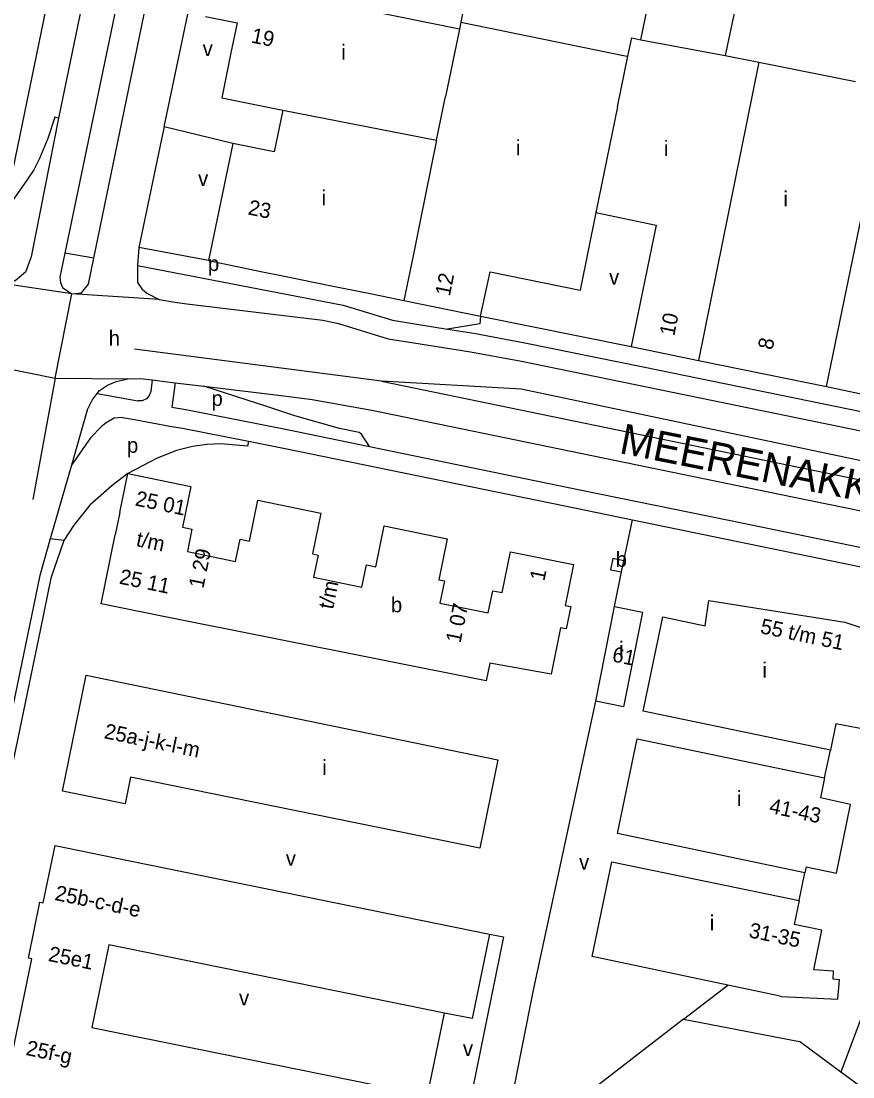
# Model space of a CAD drawing. Extents: x 157699 to 159683, y 381451 to 383293.
# Drawn here: x 158508.3 to 158727.7, y 381916.9 to 382195.6 of the extents above; entities that cross this region are included whole.
import ezdxf

# ---------------------------------------------------------------- set-up
doc = ezdxf.new("R2010")
doc.units = 0
for name, color, linetype in [('BLT_Basislijn', 7, 'Continuous'), ('BLT_Bebouwing', 7, 'Continuous'), ('BLT_Centroide', 7, 'Continuous'), ('BLT_Huisnummer', 7, 'Continuous'), ('BLT_Huisnummer_reeks', 7, 'Continuous'), ('BLT_Onderverdeling_panden', 7, 'Continuous'), ('BLT_Straatnaam_hoofdweg', 7, 'Continuous'), ('BLT_Vlakafsluiter', 7, 'Continuous')]:
    doc.layers.add(name, color=color, linetype=linetype)

msp = doc.modelspace()

# ---------------------------------------------------------------- linework, layer by layer
at = {"layer": 'BLT_Basislijn'}
for p, q in [((158564.13, 382163.27), (158546.04, 382167.67)), ((158527.49, 382132.98), (158519.79, 382134.29)), ((158557.76, 382132.36), (158539.36, 382135.84)), ((158629.49, 382117.65), (158669.22, 382109.67)), ((158517.24, 382101.36), (158511.41, 382069.28)), ((158548.94, 382100.11), (158548.05, 382093.65)), ((158720.79, 382099.1), (158736.46, 382095.81)), ((158667.27, 382053.14), (158669.58, 382063.94)), ((158664.86, 382041.02), (158666.71, 382050.22)), ((158643.57, 381940.24), (158659.86, 382016.04)), ((158720.27, 381995.8), (158721.8, 382003.12)), ((158713.57, 381963.44), (158715.04, 381970.79)), ((158683.01, 381932.1), (158694.72, 381941.12)), ((158615.51, 381911.99), (158619.97, 381933.77)), ((158683.01, 381932.1), (158634.6, 381894.79)), ((158683.01, 381932.1), (158713.62, 381926.26)), ((158724.57, 381918.14), (158713.62, 381926.26)), ((158741.51, 381905.59), (158724.57, 381918.14))]:
    msp.add_line(p, q, dxfattribs=at)
for points in [[(158542.98, 382208.18), (158560.31, 382292.99), (158566.84, 382323.44), (158566.59, 382326.28), (158565.09, 382327.85), (158564.24, 382328.17), (158561.69, 382328.03), (158560.4, 382327.07), (158559.37, 382325.83), (158558.61, 382322.72), (158542.49, 382243.35), (158519.79, 382134.29)], [(158527.49, 382132.98), (158542.98, 382208.18)], [(158524.79, 382202.3), (158518.16, 382169.99)], [(158546.04, 382167.67), (158552.26, 382197.4), (158552.33, 382197.7)], [(158518.16, 382169.99), (158517.16, 382170.25), (158515.34, 382164.61), (158513.1, 382159.29), (158511.61, 382156.3), (158509.83, 382153.6), (158506.57, 382148.93), (158504.42, 382146.04), (158502, 382143.42), (158499.11, 382140.72), (158496.4, 382138.66), (158493.14, 382136.89), (158489.59, 382135.3), (158486.33, 382134.46), (158483.25, 382133.9), (158480.45, 382133.72), (158477.19, 382133.81), (158474.02, 382134.18), (158453.69, 382138.48), (158453.19, 382136.22)], [(158518.16, 382169.99), (158510.96, 382133.33), (158509.41, 382129.31), (158506.7, 382127.02), (158505.37, 382126.57), (158502.18, 382126.47)], [(158546.04, 382167.67), (158545.35, 382164.37), (158539.36, 382135.84)], [(158519.79, 382134.29), (158518.48, 382127.97), (158518.64, 382126.54), (158519.21, 382125.27), (158521.66, 382123.63)], [(158539.36, 382135.84), (158539.01, 382131.03)], [(158521.66, 382123.63), (158524.21, 382123.84), (158526.08, 382126.15), (158527.49, 382132.98)], [(158539.01, 382131.03), (158538.95, 382126.54), (158540.15, 382124.91), (158541.45, 382123.79), (158544.73, 382122.06)], [(158539.01, 382131.03), (158593.27, 382120.63), (158606.26, 382116.63), (158612.64, 382115.59), (158620.77, 382114.29)], [(158544.73, 382122.06), (158548.84, 382121.35), (158552.02, 382120.93), (158587.89, 382116.66), (158592.01, 382115.79), (158605.12, 382111.75), (158611.85, 382110.66), (158626.88, 382108.26), (158640.25, 382105.79), (158773.96, 382078.4), (158781.03, 382076.78)], [(158629.49, 382117.65), (158629.26, 382115.71), (158620.77, 382114.29)], [(158620.77, 382114.29), (158627.72, 382113.18), (158641.21, 382110.69), (158672.43, 382104.3)], [(158603.4, 382100.5), (158538.24, 382108.95)], [(158672.43, 382104.3), (158734.22, 382091.64)], [(158528.37, 382097.25), (158528.97, 382098.04), (158531.05, 382099.44), (158533.35, 382100.44), (158536.53, 382101.17)], [(158536.53, 382101.17), (158539.79, 382101.22), (158542.83, 382100.85)], [(158542.83, 382100.85), (158542.48, 382097.85), (158542.08, 382096.71), (158541.32, 382095.86), (158540.24, 382095.36), (158539.09, 382095.32)], [(158542.83, 382100.85), (158546.21, 382100.44), (158548.94, 382100.11)], [(158548.94, 382100.11), (158556.47, 382099.2)], [(158600.15, 382083.33), (158598.05, 382086.57), (158597.47, 382086.98), (158592.31, 382088.01), (158580.47, 382091.36), (158573.35, 382093.8), (158556.47, 382099.2)], [(158603.4, 382100.5), (158713.37, 382077.85), (158775.69, 382065.11), (158780, 382064.08), (158783.9, 382063.08), (158788, 382061.52), (158792.49, 382059.17)], [(158826.34, 382042.72), (158812.46, 382052.4), (158792.15, 382064.6), (158767.88, 382071.47), (158640.23, 382098.41), (158603.4, 382100.5)], [(158525.75, 382092.88), (158527.03, 382095.5), (158528.37, 382097.25)], [(158528.37, 382097.25), (158539.09, 382095.32)], [(158585.04, 382095.72), (158600.84, 382092.86), (158711.76, 382070.02), (158773.96, 382057.3), (158778.07, 382056.31), (158781.48, 382055.44), (158784.72, 382054.21), (158788.18, 382052.4)], [(158525.75, 382092.88), (158521.58, 382078.35)], [(158548.05, 382093.65), (158551.74, 382093.05), (158578.49, 382087.79), (158600.15, 382083.33)], [(158535, 382090.98), (158532.79, 382090.73), (158530.69, 382089.57), (158529.5, 382088.6), (158526.63, 382085.6), (158521.58, 382078.35)], [(158535, 382090.98), (158538.19, 382090.4), (158547.54, 382088.67), (158550.85, 382088.13), (158568.31, 382084.69)], [(158568.31, 382084.69), (158568.05, 382083.42), (158560.99, 382083.99), (158557.28, 382083.83), (158553.52, 382083.29), (158549.26, 382082.21), (158544.18, 382080.2), (158536.44, 382076.14)], [(158568.31, 382084.69), (158577.5, 382082.89), (158655.14, 382066.9), (158669.58, 382063.94)], [(158600.15, 382083.33), (158656.15, 382071.8), (158694.96, 382063.83), (158732.57, 382056.1), (158748.9, 382052.72), (158774.02, 382047.61), (158776.64, 382046.99), (158779.39, 382046.22), (158782.2, 382045.1), (158784.45, 382043.93), (158786.62, 382042.54), (158789.07, 382040.6), (158791.02, 382038.68), (158792.82, 382036.54)], [(158521.58, 382078.35), (158515.99, 382058.89)], [(158536.44, 382076.14), (158532.32, 382073.02), (158526.43, 382067.83), (158522.18, 382062.49), (158519.56, 382058.47)], [(158669.58, 382063.94), (158693.96, 382058.93), (158731.56, 382051.2), (158734.95, 382050.5)], [(158515.99, 382058.89), (158513.23, 382049.22), (158488.25, 381928.78)], [(158519.56, 382058.47), (158515.99, 382058.89)], [(158519.56, 382058.47), (158516.14, 382048.5), (158513.38, 382035.19)], [(158513.38, 382035.19), (158491.19, 381928.17), (158487.42, 381920.58)], [(158631.83, 381954.62), (158635.53, 381953.87), (158623.19, 381893.31)], [(158640.39, 381924.33), (158643.57, 381940.24)], [(158731.44, 381936.75), (158729.4, 381931.11), (158724.57, 381918.14)], [(158634.6, 381894.79), (158640.39, 381924.33)]]:
    msp.add_lwpolyline(points, dxfattribs=at)
at = {"layer": 'BLT_Bebouwing'}
for p, q in [((158518.94, 382219.05), (158506, 382156.09)), ((158625.29, 382200.03), (158624.32, 382195.29)), ((158556.95, 382196.78), (158565.25, 382195.09)), ((158565.25, 382195.09), (158563.64, 382187.21)), ((158624.32, 382195.29), (158667.62, 382186.44)), ((158667.62, 382186.44), (158668.37, 382186.28)), ((158577.29, 382172.05), (158575.02, 382161.03)), ((158564.13, 382163.27), (158557.76, 382132.36)), ((158575.02, 382161.03), (158564.13, 382163.27)), ((158659.93, 382145.02), (158655.76, 382124.57)), ((158557.76, 382132.36), (158571.99, 382129.43)), ((158571.99, 382129.43), (158577.32, 382128.34)), ((158632.02, 382129.42), (158655.76, 382124.57)), ((158577.32, 382128.34), (158585.38, 382126.7)), ((158585.38, 382126.7), (158590.21, 382125.71)), ((158590.21, 382125.71), (158599.48, 382123.81)), ((158599.48, 382123.81), (158603.38, 382123.02)), ((158603.38, 382123.02), (158609.26, 382121.81)), ((158666.71, 382050.22), (158667.27, 382053.14)), ((158677.59, 382038.35), (158688.71, 382035.93)), ((158525.48, 382022.92), (158634.02, 382000.56)), ((158634.02, 382000.56), (158629.29, 381977.26)), ((158658.96, 381948.67), (158664.13, 381973.71)), ((158510.25, 381948.27), (158513.25, 381963.05)), ((158531.41, 381951.74), (158526.98, 381929.97)), ((158619.97, 381933.77), (158531.41, 381951.74)), ((158505.15, 381918.91), (158511.11, 381948.09)), ((158511.11, 381948.09), (158510.25, 381948.27)), ((158694.72, 381941.12), (158658.96, 381948.67)), ((158708.53, 381938.2), (158694.72, 381941.12)), ((158526.98, 381929.97), (158615.51, 381911.99))]:
    msp.add_line(p, q, dxfattribs=at)
for points in [[(158671.81, 382190.67), (158680.46, 382232.95), (158678.02, 382233.45), (158682.37, 382254.34)], [(158668.37, 382186.28), (158669.37, 382191.17), (158671.81, 382190.67)], [(158563.64, 382187.21), (158561.22, 382175.36), (158577.29, 382172.05)], [(158720.79, 382099.1), (158730.62, 382146.93), (158746.41, 382143.69)], [(158659.93, 382145.02), (158675.79, 382141.74), (158669.22, 382109.67)], [(158629.49, 382117.65), (158632.02, 382129.42)], [(158609.26, 382121.81), (158629.49, 382117.65)], [(158669.22, 382109.67), (158686.96, 382106.03)], [(158686.96, 382106.03), (158720.79, 382099.1)], [(158534.34, 382065.85), (158536.44, 382076.14)], [(158536.44, 382076.14), (158553.1, 382072.73)], [(158553.1, 382072.73), (158550.9, 382061.96), (158553.35, 382061.46), (158552.15, 382055.58), (158564.88, 382052.97)], [(158564.88, 382052.97), (158566.08, 382058.85), (158568.53, 382058.35), (158570.74, 382069.13)], [(158570.74, 382069.13), (158587.39, 382065.72)], [(158534.34, 382065.85), (158533.14, 382059.97)], [(158587.39, 382065.72), (158585.19, 382054.95), (158586.66, 382054.65), (158585.46, 382048.77), (158598.19, 382046.17)], [(158598.19, 382046.17), (158599.4, 382052.04), (158601.84, 382051.54), (158604.05, 382062.32)], [(158604.05, 382062.32), (158620.7, 382058.92)], [(158630.99, 382021.43), (158545.88, 382038.38), (158529.42, 382041.75), (158533.14, 382059.97)], [(158620.7, 382058.92), (158618.5, 382048.14), (158619.97, 382047.84), (158618.77, 382041.96), (158631.51, 382039.36)], [(158631.51, 382039.36), (158632.71, 382045.24), (158635.16, 382044.74), (158637.36, 382055.51)], [(158637.36, 382055.51), (158654.01, 382052.11)], [(158667.27, 382053.14), (158664.37, 382053.7), (158663.8, 382050.78), (158666.71, 382050.22)], [(158654.01, 382052.11), (158651.81, 382041.33), (158653.28, 382041.03)], [(158688.71, 382035.93), (158689.74, 382042.67)], [(158689.74, 382042.67), (158725.62, 382036.91), (158739.81, 382032.19)], [(158653.28, 382041.03), (158652.08, 382035.15), (158650.61, 382035.45), (158648.11, 382023.21), (158631.93, 382026.11), (158630.99, 382021.43)], [(158664.86, 382041.02), (158672.2, 382039.56), (158667.2, 382014.57), (158659.86, 382016.04)], [(158659.86, 382016.04), (158664.86, 382041.02)], [(158721.8, 382003.12), (158672.38, 382013.41), (158677.59, 382038.35)], [(158739.81, 382032.19), (158737.6, 382025.35), (158734.29, 382026.43), (158730.57, 382008.65), (158723.26, 382010.13)], [(158629.29, 381977.26), (158537.16, 381995.98), (158535.73, 381989), (158519.18, 381992.34), (158525.48, 382022.92)], [(158723.26, 382010.13), (158721.8, 382003.12)], [(158715.04, 381970.79), (158665.64, 381981.15), (158670.85, 382006.13)], [(158670.85, 382006.13), (158720.27, 381995.8)], [(158720.27, 381995.8), (158719.19, 381990.57)], [(158715.39, 381972.39), (158723.39, 381970.69), (158727.13, 381988.77), (158719.19, 381990.57)], [(158513.25, 381963.05), (158514.13, 381962.87), (158517.25, 381977.95), (158532.63, 381974.81)], [(158532.63, 381974.81), (158631.83, 381954.62)], [(158664.13, 381973.71), (158713.57, 381963.44)], [(158715.39, 381972.39), (158715.04, 381970.79)], [(158713.57, 381963.44), (158712.25, 381957.14)], [(158724.19, 381942.5), (158722.49, 381942.71), (158722.6, 381944.83), (158717.38, 381945.14), (158719.54, 381955.63), (158712.25, 381957.14)], [(158631.83, 381954.62), (158627.28, 381932.28), (158619.97, 381933.77)], [(158708.53, 381938.2), (158708.84, 381938.14), (158723.75, 381937.43), (158724.19, 381942.5)]]:
    msp.add_lwpolyline(points, dxfattribs=at)
at = {"layer": 'BLT_Onderverdeling_panden'}
for p, q in [((158703.87, 382232.93), (158694.03, 382186.49)), ((158623.95, 382193.48), (158558.96, 382206.64)), ((158623.95, 382193.48), (158620.28, 382175.71)), ((158624.32, 382195.29), (158623.95, 382193.48)), ((158671.81, 382190.67), (158694.03, 382186.49)), ((158665.62, 382172.94), (158668.37, 382186.28)), ((158702.89, 382184.73), (158686.96, 382106.03)), ((158694.03, 382186.49), (158702.89, 382184.73)), ((158702.89, 382184.73), (158728.38, 382179.66)), ((158617.91, 382164.11), (158620.28, 382175.71)), ((158577.29, 382172.05), (158617.91, 382164.11)), ((158665.62, 382172.94), (158659.93, 382145.02)), ((158617.91, 382164.11), (158613.57, 382142.89)), ((158613.57, 382142.89), (158611.67, 382133.58)), ((158611.67, 382133.58), (158609.26, 382121.81))]:
    msp.add_line(p, q, dxfattribs=at)
at = {"layer": 'BLT_Vlakafsluiter'}
for p, q in [((158521.66, 382123.63), (158502.18, 382126.47)), ((158517.24, 382101.36), (158521.66, 382123.63)), ((158544.73, 382122.06), (158521.66, 382123.63)), ((158497.16, 382105.39), (158517.24, 382101.36)), ((158517.24, 382101.36), (158536.53, 382101.17))]:
    msp.add_line(p, q, dxfattribs=at)
msp.add_lwpolyline([(158556.47, 382099.2), (158576.86, 382096.79), (158585.04, 382095.72)], dxfattribs=at)

# ---------------------------------------------------------------- texts
at = {"layer": 'BLT_Centroide'}
for s, p in [('v', (158556.18, 382186.33)), ('i', (158592.77, 382185.38)), ('i', (158638.81, 382160.17)), ('i', (158677.88, 382160)), ('v', (158554.98, 382152.06)), ('i', (158587.58, 382146.94)), ('i', (158709.39, 382146.66)), ('p', (158557.57, 382129.6)), ('v', (158663.4, 382126.05)), ('h', (158531.39, 382109.89)), ('p', (158558.52, 382094)), ('p', (158536.22, 382081.63)), ('b', (158665.14, 382051.53)), ('b', (158605.85, 382039.53)), ('i', (158666.03, 382027.8)), ('i', (158703.84, 382022.31)), ('i', (158587.72, 381996.57)), ('i', (158697.11, 381988.41)), ('v', (158578.12, 381972.62)), ('v', (158655.48, 381971.62)), ('i', (158689.96, 381955.56)), ('v', (158565.77, 381935.76)), ('v', (158624.84, 381922.41))]:
    msp.add_text(s, height=4, dxfattribs=at).set_placement(p)
at = {"layer": 'BLT_Huisnummer'}
for s, rotation, p in [('19', 348.45, (158568.78, 382189.94)), ('23', 348.4515, (158567.94, 382144.57)), ('12', 78.4506, (158621.38, 382122.8)), ('10', 78.3927, (158680.56, 382112.25)), ('8', 78.3927, (158706.5, 382108.62)), ('61', 348.7186, (158664, 382026.58))]:
    msp.add_text(s, height=4, rotation=rotation, dxfattribs=at).set_placement(p)
at = {"layer": 'BLT_Huisnummer_reeks'}
for s, rotation, p in [('25 01', 348.3189, (158538.17, 382067.75)), ('t/m', 348.3189, (158538.43, 382057.04)), ('1 29', 78.4494, (158556.35, 382045.67)), ('25 11', 348.3189, (158533.97, 382047.12)), ('1', 78.4494, (158646.32, 382047.62)), ('t/m', 78.4494, (158590.56, 382040.15)), ('1 07', 78.4494, (158624.18, 382031.24)), ('55 t/m 51', 348.1965, (158703.08, 382034.05)), ('25a-j-k-l-m', 348.3189, (158529.98, 382006.32)), ('41-43', 348.1941, (158705.45, 381986.61)), ('25b-c-d-e', 348.3189, (158516.97, 381963.63)), ('31-35', 348.2608, (158700.05, 381953.79)), ('25e1', 348.4481, (158515.25, 381947.54)), ('25f-g', 348.3189, (158509.34, 381922.72))]:
    msp.add_text(s, height=4, rotation=rotation, dxfattribs=at).set_placement(p)
at = {"layer": 'BLT_Straatnaam_hoofdweg'}
msp.add_text('MEERENAKKERWEG', height=8, rotation=348.7122, dxfattribs=at).set_placement((158665.82, 382081.59))

doc.saveas('drawing.dxf')
